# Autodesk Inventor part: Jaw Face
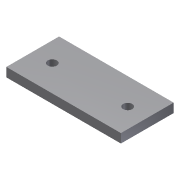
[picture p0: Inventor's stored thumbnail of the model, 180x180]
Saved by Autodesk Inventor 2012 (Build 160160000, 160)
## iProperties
Shininess: 77.0
Length Units: 11269
Angle Units: 11279
Time Units: 11290
Mass Units: 11283
Length Display Precision: 3
Angle Display Precision: 2
Compacted: True
Created: 2002-02
Part Number: Jaw Face
Document SubType Name: Modeling
Designer: ***
Density: 1 g/cm^3
Material: Default
Density: 0.0
Volumn: 0.0
Area: 0.0
PropertySet Name: Model Information
Control State: 0
Master: False
Checked Out: False
Author: ***
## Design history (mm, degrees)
sketch "Sketch1"
  geometry: L1 (-79.661, -8.43)-(-3.661, -8.43); L2 (-3.661, -8.43)-(-3.661, -43.43); L3 (-3.661, -43.43)-(-79.661, -43.43); L4 (-79.661, -43.43)-(-79.661, -8.43); C1 r 3 at (-66.661, -25.93); C2 r 3 at (-16.661, -25.93)
  constraints: 8 end point, 2 centre point, 2 parallel, 1 equal radius, 1 horizontal, 1 perpendicular
  dimensions: "d0" = 76 distance of L2.end L3.end; "d1" = 6 diameter of C1; "d2" = 50 distance of C2.centre C1.centre; "d3" = 35 distance of L1.end L2.end; "d4" = 17.5 distance from line of L3 C2.centre; "d5" = 13 distance from line of L2 C2.centre; "d6" = 13 distance from line of L4 C1.centre
extrude "Extrusion1" new body sketch "Sketch1" stored distance "d7" = 6; taper "d8" = 0 deg
body "Solid1"
